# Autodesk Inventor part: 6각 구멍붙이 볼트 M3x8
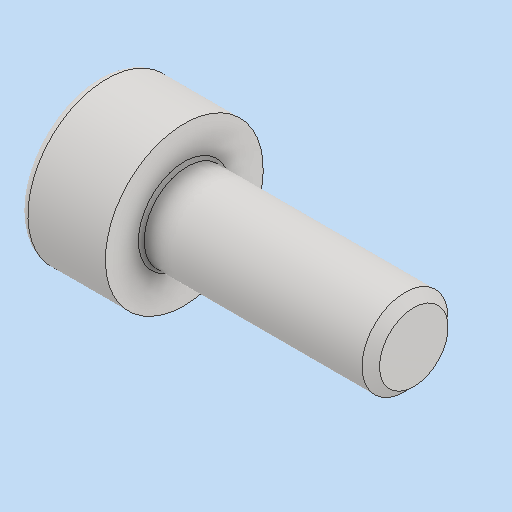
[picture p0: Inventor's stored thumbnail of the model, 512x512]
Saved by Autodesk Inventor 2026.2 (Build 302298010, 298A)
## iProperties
Created: 2026-08
Part Number: 6각 구멍붙이 볼트 M3x8
Material: 스테인리스강
Description: 6각 소켓 머리 캡 나사
Document SubType Name: Modeling
Designer: PC-2-06
Density: 8.08 g/cm^3
Appearance: 기본값
Author: jhkim
Sending System: Autodesk Inventor 2027
Preprocessor: ST-DEVELOPER v20.1
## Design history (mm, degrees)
feature "Solid1"
node "솔리드1"
